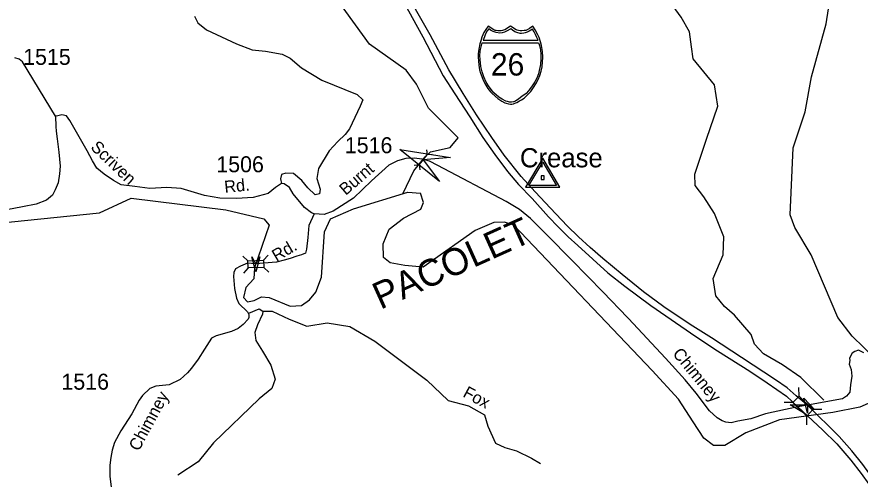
# Model space of a CAD drawing. Extents: x 990631 to 1056237, y 535999 to 585651.
# Drawn here: x 1042549 to 1049136, y 547778 to 551391 of the extents above; entities that cross this region are included whole.
import ezdxf

# ---------------------------------------------------------------- set-up
doc = ezdxf.new("R2010")
doc.units = 0
for name, color, linetype in [('Exist Hydrographic Creek Single Shore', 7, 'Continuous'), ('Exist Hydrographic River Shore', 7, 'Continuous'), ('Exist Hydrographic River Shore Label', 7, 'Continuous'), ('Exist Road Non-System Type 51', 7, 'Continuous'), ('Exist Road Non-System Type 51 Label', 7, 'Continuous'), ('Exist Road Primary Interstate Divided Center Attributed', 7, 'Continuous'), ('Exist Road Primary Interstate Shield CELL', 7, 'Continuous'), ('Exist Road Primary Interstate Shield Number Label', 7, 'Continuous'), ('Exist Road Primary US Structure Standard Bridge CELL', 7, 'Continuous'), ('Exist Road Secondary Structure Culvert Attributed CELL', 7, 'Continuous'), ('Exist Road Secondary Structure Culvert CELL', 7, 'Continuous'), ('Exist Road Secondary Structure Standard Bridge Attributed CELL', 7, 'Continuous'), ('Exist Road Secondary Structure Standard Bridge CELL', 7, 'Continuous'), ('Exist Road Secondary Type 41 Attributed', 7, 'Continuous'), ('Exist Road Secondary Type 51 Attributed', 7, 'Continuous'), ('Exist Road Secondary Type 51 Label', 7, 'Continuous'), ('Exist Road Secondary Type 51 Number Label', 7, 'Continuous'), ('Exist Survey Geodetic Marker CELL', 7, 'Continuous'), ('Exist Survey Geodetic Marker Label', 7, 'Continuous')]:
    doc.layers.add(name, color=color, linetype=linetype)

msp = doc.modelspace()

# ---------------------------------------------------------------- linework, layer by layer
at = {"layer": 'Exist Hydrographic Creek Single Shore'}
for points in [[(1049445.6, 548500.3), (1049438.6, 548539.9), (1049074.6, 548895.1), (1048962.6, 549041.8), (1048753.5, 549531.7), (1048626.9, 549744.3), (1048588.6, 549843.6), (1048613.7, 550368.2), (1048706.6, 550648.6), (1048756.5, 550923.2), (1048869.5, 551337.8), (1048953.6, 551874.3), (1049308.5, 552530.1), (1049408.5, 553053.3), (1049407.6, 553269.9), (1049534.5, 553858.1), (1049551.5, 553884), (1049619.5, 554181.3)], [(1045564.2, 550006.6), (1045650.1, 550188.5), (1045739.3, 550297.6), (1045779, 550337.3), (1045934.3, 550370.3), (1045997.1, 550446.4), (1045763.4, 550678.3), (1045669.3, 550864), (1045589.4, 550973.9), (1045304.2, 551176.5), (1045064.8, 551509.6), (1044837.9, 551983.4), (1044773.1, 552293.3), (1044748.6, 552310.1), (1044652.4, 552955.3)]]:
    msp.add_lwpolyline(points, dxfattribs=at)
at = {"layer": 'Exist Hydrographic River Shore'}
for points in [[(1042275, 549764.4), (1043193.8, 549860.3), (1043441, 549974.3), (1044181.2, 549881.7), (1044478.6, 549812.2), (1044518.3, 549762.6), (1044405.4, 549430.4), (1044399.3, 549342.7), (1044336.5, 549276.5), (1044320, 549197.2), (1044349.7, 549164.1), (1044402.6, 549174), (1044458.8, 549203.8), (1044518.3, 549197.2), (1044683.5, 549131), (1044772.7, 549134.3), (1044835.5, 549180.6), (1044883.4, 549238.8), (1044928, 549355.9), (1044951.2, 549709.7), (1044997.4, 549812.2), (1045179.2, 549891.6), (1045602.2, 550020.6), (1045700.3, 550013.3)], [(1049386.5, 548452.3), (1049133.3, 548339.8), (1048922.3, 548298.6), (1048505.5, 548242), (1048243, 548139), (1048078.4, 548041.1), (1047990.9, 548041.1), (1047913.7, 548097.8), (1047831.6, 548227.1), (1047716.9, 548403.9), (1047512.3, 548628.2), (1046430, 549761.9), (1046357.3, 549786.7), (1046274.7, 549785), (1046129.3, 549722.2), (1045723.7, 549435.3), (1045579, 549448.5), (1045463.4, 549468.3), (1045413.8, 549511.3), (1045410.5, 549617.1), (1045456.8, 549732.9), (1045569.1, 549818.8), (1045704.7, 549888.5), (1045724.4, 549941.2), (1045700.3, 550013.3)]]:
    msp.add_lwpolyline(points, dxfattribs=at)
at = {"layer": 'Exist Road Non-System Type 51'}
for points in [[(1048852.3, 548395), (1048671.6, 548571.5), (1048528.8, 548672.4), (1048381.7, 548756.5), (1048310.3, 548832.1), (1048285.1, 548907.8), (1048154.8, 549059.1), (1048075, 549126.4), (1048007.7, 549210.5), (1047986.7, 549345), (1048066.6, 549529.9), (1048070.8, 549672.8), (1047999.3, 549853.6), (1047915.3, 549983.9), (1047848.1, 550072.2), (1047843.9, 550160.5), (1047936.3, 550436.2), (1048024.6, 550692.6), (1047999.3, 550860.8), (1047831.3, 551062.5), (1047818.7, 551157.1), (1047801.9, 551274.8), (1047738.8, 551388.3), (1047646.4, 551514.4)], [(1043936.9, 551397.6), (1043962, 551343.2), (1044028.9, 551288.8), (1044263, 551180.1), (1044387.5, 551134.1), (1044492, 551121.6), (1044621.6, 551100.7), (1044684.3, 551067.2), (1044772.1, 550991.9), (1044930.9, 550895.7), (1045206, 550784.1), (1045252, 550742.3), (1045231.1, 550692.1), (1045147.5, 550516.4), (1045114, 550470.4), (1045055.5, 550416.1), (1044988.6, 550345), (1044905, 550207), (1044892.5, 550127.5), (1044917.6, 550043.9), (1044913.4, 550007.5), (1044879.9, 549999.1), (1044821.4, 550053.5), (1044775.4, 550112), (1044708.6, 550166.4), (1044650, 550170.6), (1044616.6, 550158), (1044608.2, 550124.6), (1044615.2, 550089.3)], [(1044361.6, 549074.9), (1044441, 549108.4), (1044470.3, 549091.6), (1044466.1, 549066.6), (1044428.5, 548982.9), (1044407.6, 548924.4), (1044415.9, 548861.6), (1044466.1, 548778), (1044533, 548669.3), (1044566.4, 548560.5), (1044541.4, 548485.3), (1044441, 548405.8), (1044085.7, 548062.9), (1043964.5, 547912.3), (1043806.5, 547807.8)], [(1044470.3, 549091.6), (1044542.2, 549091.6), (1044676, 549028.9), (1044813.9, 548974.6), (1044972.7, 548999.6), (1045148.3, 548970.4), (1045344.8, 548857.5), (1045750.3, 548552.2), (1045917.5, 548393.3), (1046076.3, 548351.4), (1046201.7, 548280.3), (1046226.8, 548192.5), (1046288.2, 548058.7), (1046359.3, 548025.2), (1046451.3, 548000.2), (1046568.3, 547941.6), (1046639.4, 547899.8)]]:
    msp.add_lwpolyline(points, dxfattribs=at)
at = {"layer": 'Exist Road Primary Interstate Divided Center Attributed'}
for points in [[(1048723.8, 548356.2), (1048715, 548364.7), (1048637.4, 548429.4), (1048565.1, 548492.4), (1048474, 548554.1), (1048210.1, 548728.3), (1047975.7, 548882.4), (1047808.3, 548986.9), (1047603.3, 549123.6), (1047443.9, 549242.9), (1047277.8, 549376.9), (1047125.1, 549501.5), (1047027.3, 549587.3), (1046934.9, 549671.7), (1046846.5, 549758.8), (1046716.6, 549895.5), (1046596, 550022.8), (1046487.5, 550143.4), (1046356.3, 550309.5), (1046259.8, 550448.9), (1046137.9, 550625.8), (1046036.1, 550792), (1045922.3, 550978.2), (1045776.3, 551250.3), (1045600.8, 551562.5)], [(1045566, 551512.9), (1045720, 551235.5), (1045878.8, 550930), (1045969.2, 550790.6), (1046087, 550608.4), (1046188.8, 550448.9), (1046282.6, 550316.2), (1046380.4, 550183.6), (1046467.4, 550080.4), (1046573.3, 549970.5), (1046701.4, 549828.3), (1046778.2, 549750.7), (1046854.6, 549673), (1046929.6, 549603.3), (1047164, 549391.6), (1047296.6, 549287.1), (1047501.5, 549134.3), (1047851.1, 548893.1), (1048022.6, 548781.9), (1048273.1, 548622.4), (1048409.7, 548531.3), (1048559.7, 548426.8), (1048648.3, 548343.5)], [(1048648.3, 548343.5), (1048842.1, 548163), (1048954.9, 548052.9), (1049062, 547926.9), (1049143.7, 547821.1), (1049204, 547738), (1049284.4, 547609.3), (1049356.7, 547472.6), (1049425, 547329.3), (1049509.4, 547124.2), (1049549.6, 547007.6), (1049581.7, 546891.1), (1049621.9, 546762.4), (1049656.8, 546560.1), (1049680.9, 546403.3), (1049711.7, 546213), (1049746.5, 546005.3), (1049757.2, 545922.2)], [(1049819, 545894.4), (1049802.8, 546008), (1049773.3, 546174.1), (1049742.5, 546384.5), (1049721, 546522.5), (1049683.5, 546757), (1049644.7, 546887), (1049593.8, 547058.6), (1049541.6, 547196.6), (1049477.3, 547350.7), (1049390.2, 547528.9), (1049331.3, 547632.1), (1049249.5, 547760.8), (1049157.1, 547893.4), (1049071.4, 547997.9), (1048972.3, 548110.5), (1048723.8, 548356.2)]]:
    msp.add_lwpolyline(points, dxfattribs=at)
at = {"layer": 'Exist Road Primary Interstate Shield CELL'}
for points in [[(1046404.7, 550708.7), (1046414.2, 550709.6), (1046426.9, 550712), (1046439.3, 550716.1), (1046453.4, 550722.3), (1046474.2, 550733.9), (1046491, 550743.7), (1046510.3, 550756.7), (1046536.5, 550780.4), (1046562.5, 550807.8), (1046585.5, 550838.9), (1046603.7, 550867.9), (1046619.8, 550901), (1046633.2, 550931.9), (1046643.9, 550967.3), (1046651, 551001.5), (1046654.5, 551037.2), (1046656.9, 551076.8), (1046654.2, 551121.3), (1046646.5, 551166.9), (1046639.2, 551195.2), (1046628.2, 551229.2), (1046619.2, 551250.9), (1046598.4, 551289.3), (1046579.6, 551318.9), (1046552.4, 551299.7), (1046534.6, 551290.3), (1046523.8, 551285.4), (1046512.6, 551283.2), (1046492.1, 551280.7), (1046479.2, 551281.3), (1046467.3, 551284), (1046457.2, 551286.2), (1046448.9, 551290.3), (1046404.7, 551318.9), (1046360.4, 551290.3), (1046351.1, 551286), (1046341.6, 551284), (1046332.5, 551281.5), (1046317.3, 551280.7), (1046305.8, 551281.1), (1046293.9, 551283.2), (1046284.5, 551285.2), (1046274, 551290.3), (1046228.9, 551318.9), (1046211.2, 551293.2), (1046196.7, 551267.8), (1046181.3, 551231.8), (1046171.8, 551204), (1046165, 551181.1), (1046156.6, 551139.2), (1046152.3, 551102.6), (1046151.6, 551076.8), (1046156.3, 551012.3), (1046163.4, 550977.9), (1046170.6, 550950.1), (1046194.5, 550890.1), (1046212.4, 550856.5), (1046227.8, 550832.3), (1046249.4, 550805.1), (1046261.1, 550792.2), (1046305.9, 550753), (1046335.8, 550732.6), (1046359.7, 550719.7), (1046371, 550715.4), (1046388.5, 550710.5)], [(1046234.3, 551298.1), (1046223.3, 551281.2), (1046210.6, 551258.4), (1046200.5, 551234.7), (1046190.1, 551208.5), (1046621.7, 551208.4), (1046611.6, 551230.8), (1046600.9, 551253.3), (1046589.6, 551273.9), (1046575.9, 551293.8), (1046551.7, 551278.6), (1046534.1, 551270.2), (1046519.9, 551265.3), (1046507.9, 551262.6), (1046489.3, 551261.2), (1046481, 551261.7), (1046455, 551267.5), (1046437.5, 551274.7), (1046420.8, 551285.9), (1046407.3, 551298.6), (1046373.1, 551277.9), (1046357.9, 551271.2), (1046340.5, 551266.8), (1046321.4, 551264.4), (1046292, 551267.5), (1046268.9, 551275.5), (1046249, 551285.9)], [(1046624.2, 551187.1), (1046628.8, 551174.9), (1046635.2, 551147.9), (1046638.5, 551127), (1046642, 551103), (1046640.8, 551061.9), (1046638.8, 551019.3), (1046634.9, 550994.1), (1046629.6, 550971.2), (1046622.5, 550945.7), (1046610.9, 550911.9), (1046595, 550883.2), (1046575.1, 550851.4), (1046553.7, 550823.5), (1046544.3, 550812), (1046526.6, 550793.3), (1046494.4, 550767.4), (1046470.9, 550749.8), (1046442.7, 550733.2), (1046428.4, 550726.8), (1046411.7, 550723.4), (1046398, 550724.3), (1046381.4, 550728.7), (1046368, 550732.4), (1046338.5, 550748.3), (1046314.7, 550764.3), (1046274.9, 550796.9), (1046253.5, 550822), (1046233.4, 550851.4), (1046215.5, 550881.5), (1046196.5, 550921.1), (1046183, 550961.1), (1046173.2, 551004.1), (1046166.6, 551056.8), (1046165.9, 551088.8), (1046167.8, 551119.7), (1046170.8, 551135.8), (1046174.7, 551155.9), (1046182.6, 551186.9)]]:
    msp.add_lwpolyline(points, close=True, dxfattribs=at)
at = {"layer": 'Exist Road Primary US Structure Standard Bridge CELL'}
for p, q in [((1048658.8, 548426.2), (1048658.1, 548495.2)), ((1048610.5, 548376.9), (1048541.5, 548376.2)), ((1048836.6, 548322.1), (1048767.6, 548321.4)), ((1048719, 548202), (1048718.2, 548271))]:
    msp.add_line(p, q, dxfattribs=at)
msp.add_lwpolyline([(1048718.2, 548271), (1048610.3, 548376.7), (1048659.7, 548427.1), (1048767.6, 548321.4)], close=True, dxfattribs=at)
at = {"layer": 'Exist Road Secondary Structure Culvert Attributed CELL'}
msp.add_lwpolyline([(1045850.9, 550103.3), (1045539.9, 550354.9), (1045935, 550292.5), (1045722.7, 550273.6)], close=True, dxfattribs=at)
at = {"layer": 'Exist Road Secondary Structure Culvert CELL'}
for p, q in [((1045692.5, 550235.9), (1045752.9, 550311.4)), ((1045747.3, 550351.6), (1045752.9, 550311.4)), ((1045793.4, 550314.8), (1045752.9, 550311.4)), ((1045652, 550232.5), (1045692.5, 550235.9)), ((1045698.1, 550195.6), (1045692.5, 550235.9))]:
    msp.add_line(p, q, dxfattribs=at)
at = {"layer": 'Exist Road Secondary Structure Standard Bridge Attributed CELL'}
for points in [[(1044446.2, 549516.2), (1044414.6, 549398.5), (1044383, 549516.2), (1044414.6, 549459.4)], [(1048724.1, 548292.7), (1048695.2, 548411.2), (1048779.4, 548323), (1048724.5, 548357.7)], [(1048694.4, 548297.3), (1048588.7, 548357.9), (1048710.6, 548358.3), (1048647.6, 548342.3)]]:
    msp.add_lwpolyline(points, close=True, dxfattribs=at)
at = {"layer": 'Exist Road Secondary Structure Standard Bridge CELL'}
for p, q in [((1044353.9, 549483.9), (1044313.5, 549521.5)), ((1044512.3, 549529.6), (1044474.7, 549489.2)), ((1044355.9, 549428.7), (1044318.3, 549388.3)), ((1044517.1, 549395.2), (1044476.7, 549432.8))]:
    msp.add_line(p, q, dxfattribs=at)
msp.add_lwpolyline([(1044476.7, 549432.8), (1044355.9, 549428.5), (1044353.9, 549484.9), (1044474.7, 549489.2)], close=True, dxfattribs=at)
at = {"layer": 'Exist Road Secondary Type 41 Attributed'}
for points in [[(1042850.7, 550613.7), (1042853.5, 550534), (1042856.4, 550497.9), (1042862.6, 550437.8), (1042875.3, 550333.3), (1042887.7, 550224.8), (1042881.7, 550164.9), (1042871.5, 550093.3), (1042847.7, 550037.9), (1042826.3, 549998.5), (1042781.1, 549958), (1042700.2, 549926.3), (1042591.5, 549906.7), (1042469.2, 549884)], [(1044871.4, 549852.8), (1044849.6, 549859.4), (1044794.9, 549900.4), (1044706.2, 550007.4), (1044678.9, 550057.5), (1044636.3, 550084.7), (1044615.2, 550089.3), (1044569.7, 550057.5), (1044510.5, 550009.7), (1044394.4, 549980.1), (1044264.7, 549970.9), (1044135, 549973.2), (1044014.4, 549996), (1043832.4, 550050.6), (1043720.9, 550057.5), (1043586.6, 550050.6), (1043470.6, 550064.3), (1043363.6, 550078), (1043302.2, 550112.1), (1043229.4, 550162.2), (1043172.5, 550207.7), (1043138.4, 550266.9), (1043097.4, 550344.4), (1042962.9, 550582), (1042937.3, 550618.3), (1042901, 550624.3), (1042867.8, 550616.8), (1042850.7, 550613.7)], [(1048648.3, 548343.5), (1048397.2, 548289), (1048282, 548250.5), (1048180.9, 548231.4), (1048128.6, 548217.7), (1048087.6, 548222.3), (1048058, 548233.7), (1048019.4, 548256.4), (1047959.7, 548311), (1047854.1, 548450.3), (1047769.3, 548553.1), (1047614.7, 548722.3), (1047326.4, 549033.8), (1047318.8, 549041.7), (1047128.9, 549238.2), (1046882.9, 549490.3), (1046690.9, 549684.4), (1046608.5, 549768.3), (1046560.7, 549816.1), (1046474.3, 549884.4), (1046369.6, 549948.2), (1045837.1, 550230.5), (1045771.1, 550262.4), (1045714.2, 550278.3), (1045652.8, 550287.4), (1045586.8, 550282.9), (1045520.8, 550266.9), (1045454.8, 550232.8), (1045318.3, 550109.8), (1045178.8, 549972.8), (1045020.2, 549873), (1044949, 549847.4), (1044871.4, 549852.8)], [(1044871.4, 549852.8), (1044828, 549760.3), (1044822.2, 549665.8), (1044810.9, 549574.8), (1044804, 549542.9), (1044772.2, 549532.3), (1044736.8, 549519.5), (1044683.9, 549503.6), (1044637.2, 549490.5), (1044576.2, 549472.8), (1044412.7, 549460.9)], [(1044412.7, 549460.9), (1044351.2, 549465.5), (1044294.9, 549442.2), (1044257, 549420.5), (1044244, 549393.5), (1044241.9, 549361), (1044249.4, 549266.7), (1044263.5, 549193), (1044283, 549149.7), (1044351.2, 549085.8), (1044359.9, 549064.1), (1044360.8, 549040.7), (1044356.3, 549027), (1044316.9, 548986.2), (1044304.6, 548976.5), (1044277.8, 548955.3), (1044224.5, 548930.8), (1044105.4, 548897.2), (1044070.2, 548879.4), (1044014.5, 548793.8), (1043964.1, 548715.2), (1043913.6, 548644.7), (1043880.5, 548607.8), (1043822.9, 548557.7), (1043737.3, 548514.4), (1043634.5, 548505), (1043587.9, 548487.3), (1043530.6, 548431), (1043503.5, 548395.7), (1043446.1, 548289.6), (1043359.9, 548155.6), (1043312.3, 548064.6), (1043292.8, 548003.9), (1043282, 547947.6), (1043275.5, 547886.9), (1043275.5, 547802.4), (1043284.1, 547715.7)], [(1049163.9, 548764.2), (1049123, 548784.7), (1049093.4, 548775.6), (1049072.9, 548761.9), (1049053.6, 548724.1), (1049054.7, 548705), (1049050.2, 548677.7), (1049066.1, 548634.4), (1049070.6, 548582), (1049061.5, 548516), (1049054.7, 548456.8), (1049029.7, 548427.2), (1048997.8, 548406.7), (1048723.8, 548356.2)], [(1048723.8, 548356.2), (1048648.3, 548343.5)]]:
    msp.add_lwpolyline(points, dxfattribs=at)
at = {"layer": 'Exist Road Secondary Type 51 Attributed'}
msp.add_lwpolyline([(1042850.7, 550613.7), (1042593, 551038.3), (1042567.3, 551059.5), (1042532.6, 551071.5)], dxfattribs=at)
at = {"layer": 'Exist Survey Geodetic Marker CELL'}
for points in [[(1046790.4, 550060.9), (1046656.4, 550286.9), (1046523, 550060.9)], [(1046764.5, 550073), (1046549, 550073), (1046656.4, 550255.1)], [(1046668.8, 550119.6), (1046668.8, 550147.8), (1046644.5, 550147.8), (1046644.5, 550119.6)]]:
    msp.add_lwpolyline(points, close=True, dxfattribs=at)

# ---------------------------------------------------------------- texts
at = {"layer": 'Exist Hydrographic River Shore Label'}
msp.add_text('PACOLET', height=210, rotation=24.28937, dxfattribs=at).set_placement((1045388.8, 549100.5))
at = {"layer": 'Exist Road Non-System Type 51 Label'}
msp.add_text('Fox', height=95, rotation=331.74671, dxfattribs=at).set_placement((1046026, 548426))
at = {"layer": 'Exist Road Primary Interstate Shield Number Label'}
msp.add_text('26', height=175, dxfattribs=at).set_placement((1046251.8, 550932.4))
at = {"layer": 'Exist Road Secondary Type 51 Label'}
for s, rotation, p in [('Scriven', 316.15161, (1043118.3, 550364.5)), ('Burnt', 40.54222, (1045117.4, 549991.5)), ('Rd.', 5.91795, (1044173.8, 550014.1)), ('Rd.', 30.5265, (1044576.3, 549474.8)), ('Chimney', 309.5211, (1047665.7, 548756)), ('Chimney', 61.6013, (1043500.4, 547989.9))]:
    msp.add_text(s, height=95, rotation=rotation, dxfattribs=at).set_placement(p)
at = {"layer": 'Exist Road Secondary Type 51 Number Label'}
for s, p in [('1515', (1042597.5, 551015.9)), ('1516', (1045110.3, 550325.3)), ('1506', (1044106.4, 550176.3)), ('1516', (1042896.4, 548477.1))]:
    msp.add_text(s, height=125, dxfattribs=at).set_placement(p)
at = {"layer": 'Exist Survey Geodetic Marker Label'}
msp.add_text('Crease', height=150, dxfattribs=at).set_placement((1046478.3, 550214.8))

doc.saveas('drawing.dxf')
